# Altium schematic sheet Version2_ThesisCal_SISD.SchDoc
size A2; SheetNumber: 1; SheetTotal: 1; SPICEModelCacheJMJTSHEM: <root> / <DocumentId>JMJTSHEM</DocumentId> / </root>
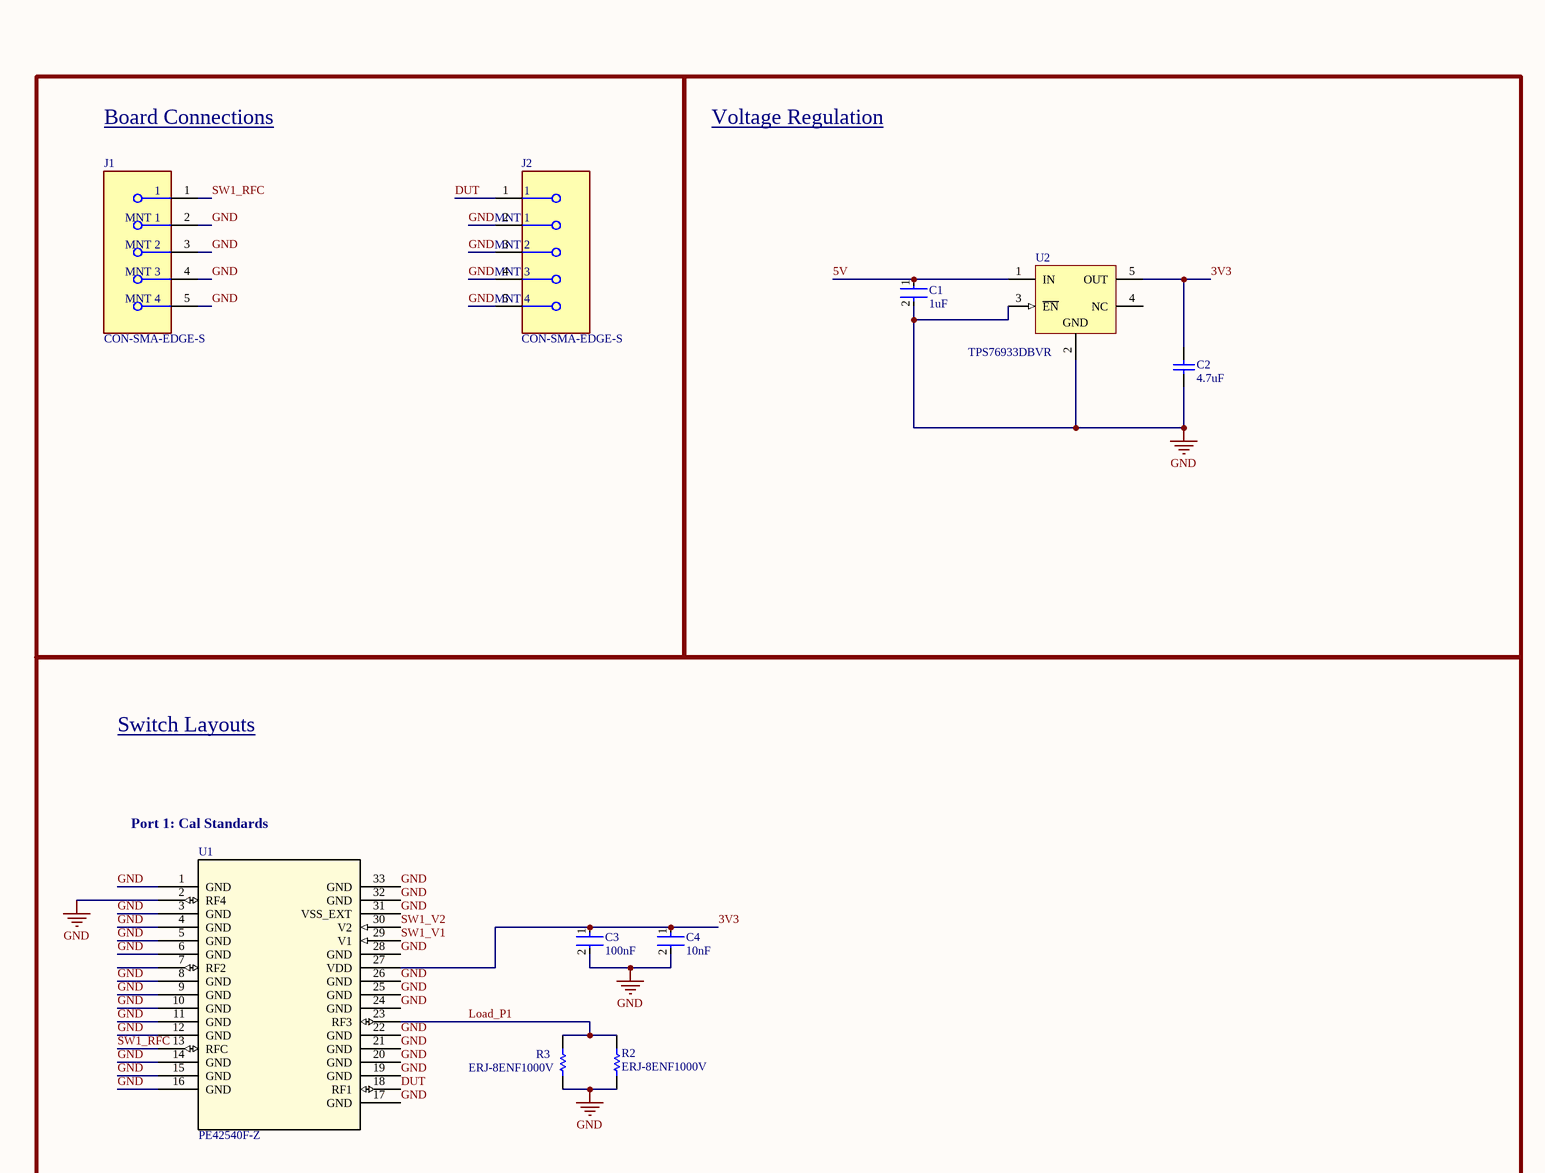
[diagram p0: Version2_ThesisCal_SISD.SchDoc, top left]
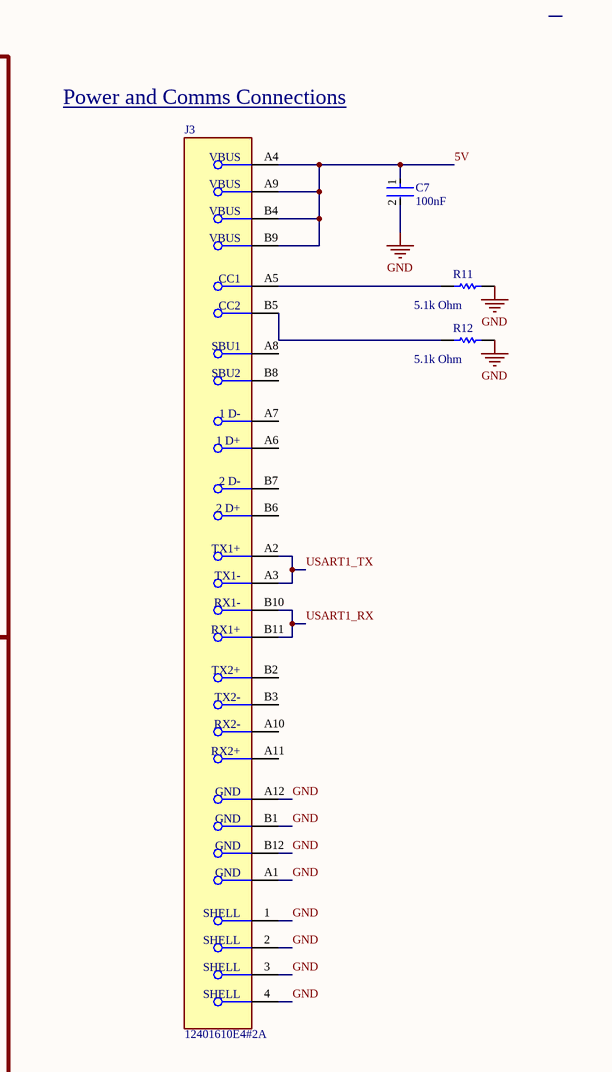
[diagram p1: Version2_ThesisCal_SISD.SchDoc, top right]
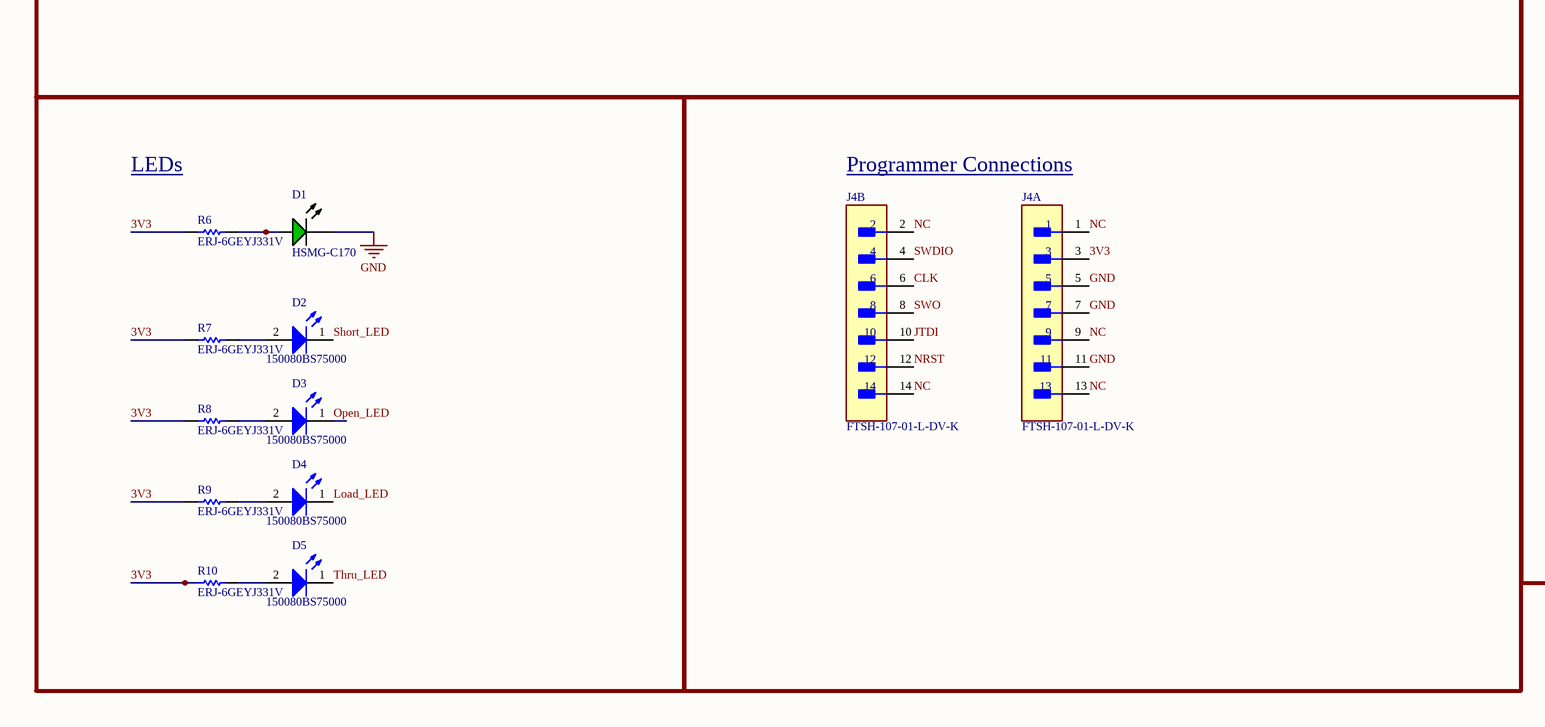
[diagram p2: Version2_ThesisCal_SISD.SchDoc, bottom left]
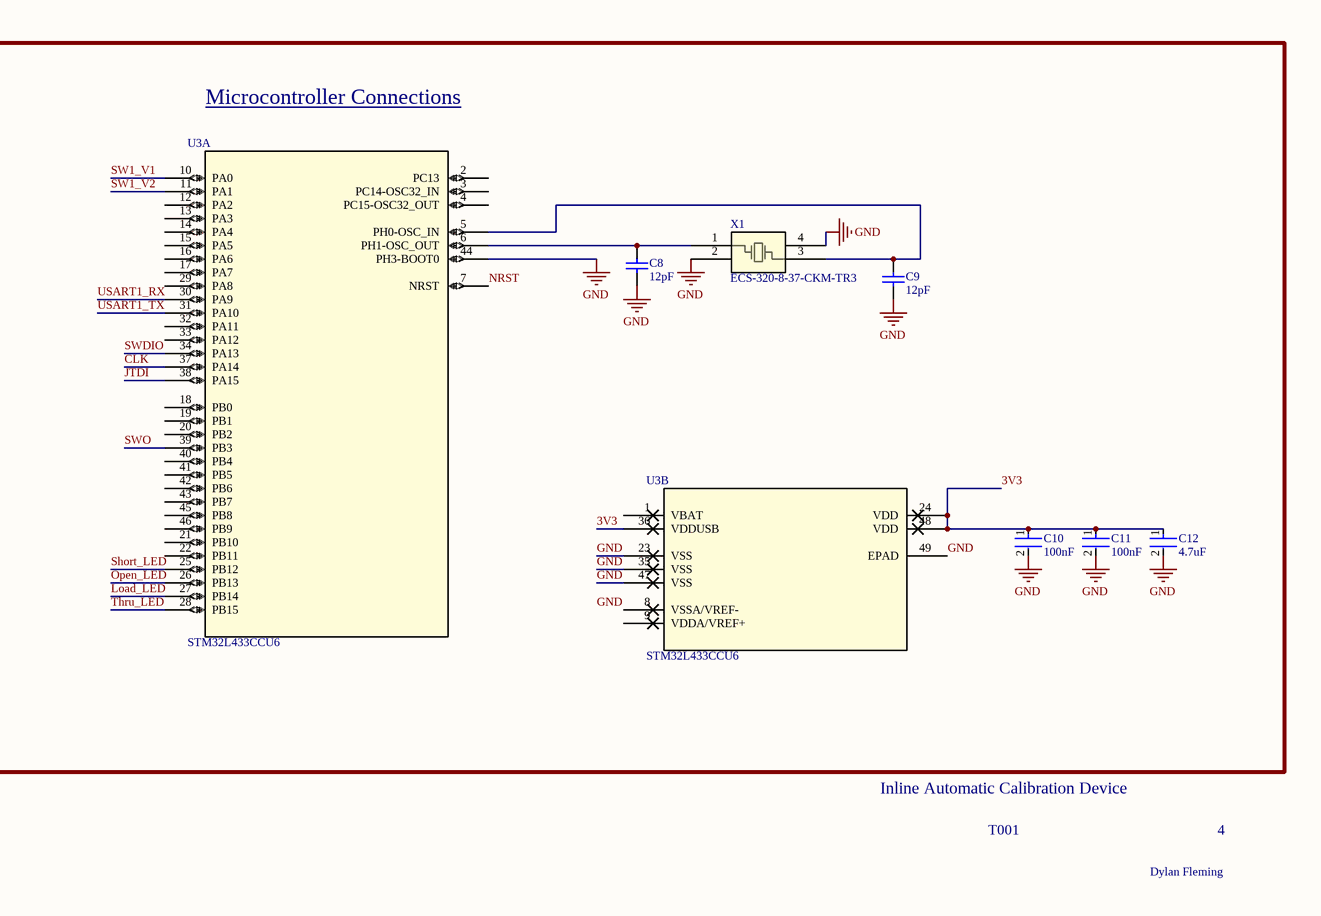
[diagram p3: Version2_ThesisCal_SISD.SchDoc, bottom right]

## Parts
C1  1uF  [FP-C1608-080-0_1-IPC_B]
C2  4.7uF  [CAPC2013X135X45LL10T25]
C3  100nF  [FP-1206-L_3_2_0_2-W_1_6_0-MFG]
C4  10nF  [FP-C0805C-DN-MFG]
C7  100nF  [FP-1206-L_3_2_0_2-W_1_6_0-MFG]
C8  12pF  [CAPC2013X115X51NL20T26]
C9  12pF  [CAPC2013X115X51NL20T26]
C10  100nF  [FP-1206-L_3_2_0_2-W_1_6_0-MFG]
C11  100nF  [FP-1206-L_3_2_0_2-W_1_6_0-MFG]
C12  4.7uF  [FP-C2012-125-0_2-IPC_C]
D1  HSMG-C170  [AVAG-HSMX-C170_V]
D2  150080BS75000  [WL-SMCW_0805_150080xx75000]
D3  150080BS75000  [WL-SMCW_0805_150080xx75000]
D4  150080BS75000  [WL-SMCW_0805_150080xx75000]
D5  150080BS75000  [WL-SMCW_0805_150080xx75000]
J1  CON-SMA-EDGE-S  [FP-CON-SMA-EDGE-S-MFG]
J2  CON-SMA-EDGE-S  [FP-CON-SMA-EDGE-S-MFG]
J3  12401610E4#2A  [FP-12401610E4#2A-MFG]
J4  FTSH-107-01-L-DV-K  [FP-FTSH-107-01-L-DV-K-MFG]  (parts A,B of 2)
R2  ERJ-8ENF1000V  [RESC3216X70X50NL05T20]
R3  ERJ-8ENF1000V  [RESC3216X70X50NL05T20]
R6  ERJ-6GEYJ331V  [RESC2013X70X40LL20T20]
R7  ERJ-6GEYJ331V  [RESC2013X70X40LL20T20]
R8  ERJ-6GEYJ331V  [RESC2013X70X40LL20T20]
R9  ERJ-6GEYJ331V  [RESC2013X70X40LL20T20]
R10  ERJ-6GEYJ331V  [RESC2013X70X40LL20T20]
R11  5.1k Ohm  [RESC3216X50X50NL20T25]
R12  5.1k Ohm  [RESC3216X50X50NL20T25]
U1  PE42540F-Z  [PE42540G-Z]
U2  TPS76933DBVR  [DBV0005A_L]
U3  STM32L433CCU6  [UFQFPN48-7x7mm]  (parts A,B of 2)
X1  ECS-320-8-37-CKM-TR3  [NX2016SA_NDK]

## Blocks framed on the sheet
Board Connections: J1 J2
Voltage Regulation: C1 C2 U2
Switch Layouts: C3 C4 R2 R3 U1
Microcontroller Connections: C8-C12 U3 X1
LEDs: D1-D5 R6-R10
Programmer Connections: J4

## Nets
GND: C1.2 C2.1 C3.2 C4.2 C7.2 C8.1 C9.1 C10.2 C11.2 C12.2 D1.2(K) J1.2(MNT_1) J1.3(MNT_2) J1.4(MNT_3) J1.5(MNT_4) J2.2(MNT_1) J2.3(MNT_2) J2.4(MNT_3) J2.5(MNT_4) J3.1(SHELL) J3.2(SHELL) J3.3(SHELL) J3.4(SHELL) J3.A1(GND) J3.A12(GND) J3.B1(GND) J3.B12(GND) J4.5 J4.7 J4.11 R2.2 R3.2 R11.2 R12.2 U1.1(GND) U1.2(RF4) U1.3(GND) U1.4(GND) U1.5(GND) U1.6(GND) U1.8(GND) U1.9(GND) U1.10(GND) U1.11(GND) U1.12(GND) U1.14(GND) U1.15(GND) U1.16(GND) U1.17(GND) U1.19(GND) U1.20(GND) U1.21(GND) U1.22(GND) U1.24(GND) U1.25(GND) U1.26(GND) U1.28(GND) U1.31(VSS_EXT) U1.32(GND) U1.33(GND) U2.2(GND) U2.3(~{EN}) U3.23(VSS) U3.35(VSS) U3.44(PH3-BOOT0) U3.47(VSS) U3.49(EPAD) X1.2 X1.4
3V3: C2.2 C3.1 C4.1 C10.1 C11.1 C12.1 J4.3 R6.1 R7.1 R8.1 R9.1 R10.1 U1.27(VDD) U2.5(OUT) U3.24(VDD) U3.36(VDDUSB) U3.48(VDD)
5V: C1.1 C7.1 J3.A4(VBUS) J3.A9(VBUS) J3.B4(VBUS) J3.B9(VBUS) U2.1(IN)
CLK: J4.6 U3.37(PA14)
DUT: J2.1 U1.18(RF1)
JTDI: J4.10 U3.38(PA15)
Load_LED: D4.1(K) U3.27(PB14)
Load_P1: R2.1 R3.1 U1.23(RF3)
NC: J4.1 J4.2 J4.9 J4.13 J4.14
NRST: J4.12 U3.7(NRST)
Open_LED: D3.1(K) U3.26(PB13)
Short_LED: D2.1(K) U3.25(PB12)
SW1_RFC: J1.1 U1.13(RFC)
SW1_V1: U1.29(V1) U3.10(PA0)
SW1_V2: U1.30(V2) U3.11(PA1)
SWDIO: J4.4 U3.34(PA13)
SWO: J4.8 U3.39(PB3)
Thru_LED: D5.1(K) U3.28(PB15)
USART1_RX: J3.B10(RX1-) J3.B11(RX1+) U3.30(PA9)
USART1_TX: J3.A2(TX1+) J3.A3(TX1-) U3.31(PA10)
NetC8_2: C8.2 U3.6(PH1-OSC_OUT) X1.1
NetC9_2: C9.2 U3.5(PH0-OSC_IN) X1.3
NetD1_1: D1.1(A) R6.2
NetD2_2: D2.2(A) R7.2
NetD3_2: D3.2(A) R8.2
NetD4_2: D4.2(A) R9.2
NetD5_2: D5.2(A) R10.2
NetJ3_A5: J3.A5(CC1) R11.1
NetJ3_B5: J3.B5(CC2) R12.1

Not connected (* = marked no-connect by the designer): J3 A6(1_D+) A7(1_D-) A8(SBU1) A10(RX2-) A11(RX2+) B2(TX2+) B3(TX2-) B6(2_D+) B7(2_D-) B8(SBU2); U1 7(RF2); U2 4(NC); U3 1(VBAT) 2(PC13) 3(PC14-OSC32_IN) 4(PC15-OSC32_OUT) 8(VSSA/VREF-) 9(VDDA/VREF+) 12(PA2) 13(PA3) 14(PA4) 15(PA5) 16(PA6) 17(PA7) 18(PB0) 19(PB1) 20(PB2) 21(PB10) 22(PB11) 29(PA8) 32(PA11) 33(PA12) 40(PB4) 41(PB5) 42(PB6) 43(PB7) 45(PB8) 46(PB9)

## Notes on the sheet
- Power and Comms Connections
- Port 1: Cal Standards
- Inline Automatic Calibration Device
- T001
- Dylan Fleming
- 4
- Labels drawn without touching a wire or pin: GND

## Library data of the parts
C1 = CMP-2000-06025-2: Multilayer Ceramic Capacitors 1μF ±10% 50V X5R SMD 0603
C2 = CMP-1662-00015-2: Chip Capacitor, 4.7 uF, +/- 10%, 16 V, -55 to 85 degC, 0805 (2012 Metric), RoHS, Tape and Reel; PartNumber: GRM21BR61C475KA88L; Voltage Rating (DC): 16 V; Type (Capacitors): X5R; Case\/Package: 0805
C3 C7 C10 C11 = CMP-04427-004798-1: General Purpose Ceramic Capacitor, 1206, 100nF, 10%, X7R, 15%, 100V
C4 = CMP-2007-00259-2: CAP CER 10000PF 200V X7R 0805; Manufacturer Part Number: C0805C103K2RACTU; Manufacturer: KEMET; Material: Ceramic; Temperature Coefficient: 30ppm/°C; Capacitance: 10,000 pF; Tolerance: 0.1; Value: 10,000 pF
C8 C9 = CMP-2007-04862-1: Manufacturer: AVX Interconnect / Elco; Part Number: 08052U120GAT2A
C12 = CMP-08246-000007-2: Multilayer Ceramic Capacitors 4.7μF ±10% 50V X5R SMD 0805
D1 = CMP-2000-05062-1: Chip LED, Green, 2.2 V, -40 to 85 degC, 2-Pin SMD, Pb-Free, Tape and Reel; Manufacturer: Avago; No. of Pins: 2; Peak Wavelength: 570nm; SVHC: NoSVHC(16-Jun-2014); Dominant Wavelength: 572nm; Forward Current If: 20mA; Viewing Angle: 170deg; Lens Shape: Rectangular; PIV Max: 5V; External Width: 1.25mm; LED Type: Standard; External Depth: 0.8mm; Opto Mounting Orientation: Top; Luminous Intensity: 15mcd; Luminous Intensity Min: 4mcd; Forward Voltage VF Max: 2.6V; External Length / Height: 2mm; Bulb Size: 1.25mmx1.4mm; Light Area Height: 1mm; Voltage Vf Typ: 2.2V
D2-D5 = CMP-1426-00008-6: NexarPartId: 29717779; Test Current: 20mA; Lens Style: Clear, Rectangular; Forward Current: 100mA; Power Dissipation: 105mW; Dominant Wavelength: 470nm; Reverse Voltage: 5V; Viewing Angle: 140°; Luminous Intensity: 145mcd; Color: Blue; Forward Voltage: 3.2V; Max Junction Temperature (Tj): 95°C; Peak Wavelength: 465nm
J1 J2 = CMP-204357-000001-1: CONN SMA JACK STR EDGE MNT; Manufacturer: RF Solutions Ltd.; Impedance: 50Ω; Conn Orientation: Right Angle; Is Female: yes; Number Of Contacts: 1; Frequency: 18GHz; Shielding: true
J3 = CMP-15126-126516878-1: 12401610E4#2A Conn USB Type C RCP 24 POS 0.5mm Solder RA SMD 24 Terminal 1 Port Automotive; Gender: Receptacle; USB Standard: USB 3.1; Number of Contacts: 24; Current Rating: 5A
J4 = CMP-02766-001412-1: CONN HEADER SMD 14POS 1.27MM; Number of Contacts: 14; Gender: Male
R2 R3 = CMP-2003-00016-1: Manufacturer: Panasonic
R6-R10 = CMP-1013-00062-2: Manufacturer: Panasonic
R11 R12 = CMP-2003-02609-1: Part Number: RG3216P-5101-B-T5; Manufacturer: Susumu
U1 = PE42540F-Z: No Description Available; Mfr_Name: Peregine Semiconductor
U2 = CMP-0394-00574-2: Single Output LDO, 100 mA, Fixed 3.3 V Output, 2.7 to 10 V Input, with Low IQ, 5-pin SOT-23 (DBV), -40 to 125 degC, Green (RoHS & no Sb/Br); Manufacturer: Texas Instruments; Fixed Output Options(V): 3.3; Iq(Typ)(mA): 0.02; Rating: Catalog; Vin(Max)(V): 10; SubFamily: Single Channel LDO; Iout(Max)(A): 0.1; Vin(Min)(V): 2.7; Accuracy(%): 3; Vdo(Typ)(mV): 98
U3 = STM32L433CCU6: No Description Available; Mfr_Name: STMicroelectronics
X1 = NX2016SA-32M-EXS00A-CS06465: No Description Available; Mfr_Name: NDK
